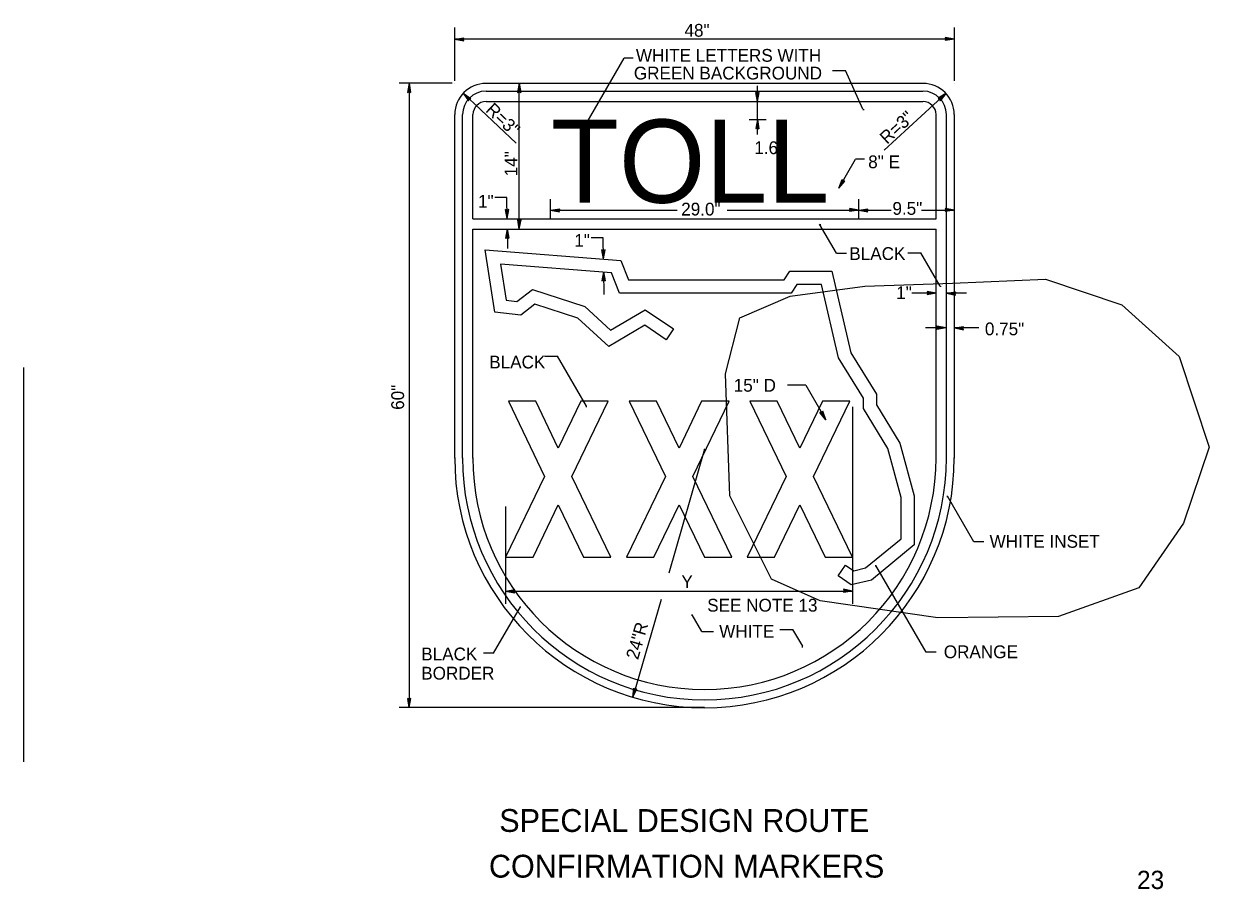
# Model space of a CAD drawing. Extents: x 51788 to 52424, y 9835 to 10249.
# Drawn here: x 52164.7 to 52424.2, y 9845.3 to 10034.8 of the extents above; entities that cross this region are included whole.
import ezdxf

# ---------------------------------------------------------------- set-up
doc = ezdxf.new("R2010")
doc.units = 0
for name, color, linetype in [('DimLines_dp', 7, 'Continuous'), ('GSColorFill', 7, 'Continuous'), ('GSDims', 7, 'Continuous'), ('SignPanel', 7, 'Continuous'), ('TextAlert', 7, 'Continuous'), ('TextMisc', 7, 'Continuous'), ('TextShtNo', 7, 'Continuous')]:
    doc.layers.add(name, color=color, linetype=linetype)

msp = doc.modelspace()

# ---------------------------------------------------------------- linework, layer by layer
at = {"layer": 'DimLines_dp'}
msp.add_line((52313.7, 9941.63), (52313.7, 9941.63), dxfattribs=at)
msp.add_line((52313.7, 9941.63), (52313.7, 9941.63), dxfattribs=at)
for radius in [0.0387, 0.0387, 0.0193]:
    msp.add_circle((52313.7, 9941.63), radius, dxfattribs=at)
at = {"layer": 'GSColorFill'}
for p, q in [((52270.76, 9952.16), (52278.69, 9935.69)), ((52276.75, 9952.16), (52270.76, 9952.16)), ((52270.76, 9952.16), (52278.69, 9935.69)), ((52276.75, 9952.16), (52270.76, 9952.16)), ((52281.69, 9941.91), (52276.75, 9952.16)), ((52281.69, 9941.91), (52276.75, 9952.16)), ((52286.63, 9952.16), (52281.69, 9941.91)), ((52286.63, 9952.16), (52281.69, 9941.91)), ((52284.69, 9935.69), (52292.63, 9952.16)), ((52284.69, 9935.69), (52292.63, 9952.16)), ((52292.63, 9952.16), (52286.63, 9952.16)), ((52292.63, 9952.16), (52286.63, 9952.16)), ((52297.2, 9952.16), (52305.13, 9935.69)), ((52303.19, 9952.16), (52297.2, 9952.16)), ((52297.2, 9952.16), (52305.13, 9935.69)), ((52303.19, 9952.16), (52297.2, 9952.16)), ((52308.13, 9941.91), (52303.19, 9952.16)), ((52308.13, 9941.91), (52303.19, 9952.16)), ((52313.07, 9952.16), (52308.13, 9941.91)), ((52313.07, 9952.16), (52308.13, 9941.91)), ((52311.13, 9935.69), (52319.07, 9952.16)), ((52311.13, 9935.69), (52319.07, 9952.16)), ((52319.07, 9952.16), (52313.07, 9952.16)), ((52319.07, 9952.16), (52313.07, 9952.16)), ((52323.64, 9952.16), (52331.58, 9935.69)), ((52329.63, 9952.16), (52323.64, 9952.16)), ((52323.64, 9952.16), (52331.58, 9935.69)), ((52329.63, 9952.16), (52323.64, 9952.16)), ((52334.57, 9941.91), (52329.63, 9952.16)), ((52334.57, 9941.91), (52329.63, 9952.16)), ((52339.51, 9952.16), (52334.57, 9941.91)), ((52339.51, 9952.16), (52334.57, 9941.91)), ((52337.57, 9935.69), (52345.51, 9952.16)), ((52337.57, 9935.69), (52345.51, 9952.16)), ((52345.51, 9952.16), (52339.51, 9952.16)), ((52345.51, 9952.16), (52339.51, 9952.16)), ((52278.69, 9935.69), (52270.16, 9917.99)), ((52278.69, 9935.69), (52270.16, 9917.99)), ((52293.22, 9917.99), (52284.69, 9935.69)), ((52293.22, 9917.99), (52284.69, 9935.69)), ((52305.13, 9935.69), (52296.6, 9917.99)), ((52305.13, 9935.69), (52296.6, 9917.99)), ((52319.66, 9917.99), (52311.13, 9935.69)), ((52319.66, 9917.99), (52311.13, 9935.69)), ((52331.58, 9935.69), (52323.05, 9917.99)), ((52331.58, 9935.69), (52323.05, 9917.99)), ((52346.1, 9917.99), (52337.57, 9935.69)), ((52346.1, 9917.99), (52337.57, 9935.69)), ((52276.16, 9917.99), (52281.69, 9929.47)), ((52276.16, 9917.99), (52281.69, 9929.47)), ((52281.69, 9929.47), (52287.22, 9917.99)), ((52281.69, 9929.47), (52287.22, 9917.99)), ((52302.6, 9917.99), (52308.13, 9929.47)), ((52302.6, 9917.99), (52308.13, 9929.47)), ((52308.13, 9929.47), (52313.67, 9917.99)), ((52308.13, 9929.47), (52313.67, 9917.99)), ((52329.04, 9917.99), (52334.57, 9929.47)), ((52329.04, 9917.99), (52334.57, 9929.47)), ((52334.57, 9929.47), (52340.11, 9917.99)), ((52334.57, 9929.47), (52340.11, 9917.99)), ((52270.16, 9917.99), (52276.16, 9917.99)), ((52270.16, 9917.99), (52276.16, 9917.99)), ((52287.22, 9917.99), (52293.22, 9917.99)), ((52287.22, 9917.99), (52293.22, 9917.99)), ((52296.6, 9917.99), (52302.6, 9917.99)), ((52296.6, 9917.99), (52302.6, 9917.99)), ((52313.67, 9917.99), (52319.66, 9917.99)), ((52313.67, 9917.99), (52319.66, 9917.99)), ((52323.05, 9917.99), (52329.04, 9917.99)), ((52323.05, 9917.99), (52329.04, 9917.99)), ((52340.11, 9917.99), (52346.1, 9917.99)), ((52340.11, 9917.99), (52346.1, 9917.99))]:
    msp.add_line(p, q, dxfattribs=at)
for points in [[(52270.76, 9952.16), (52278.69, 9935.69), (52270.16, 9917.99), (52276.16, 9917.99), (52281.69, 9929.47), (52287.22, 9917.99), (52293.22, 9917.99), (52284.69, 9935.69), (52292.63, 9952.16), (52286.63, 9952.16), (52281.69, 9941.91), (52276.75, 9952.16)], [(52297.2, 9952.16), (52305.13, 9935.69), (52296.6, 9917.99), (52302.6, 9917.99), (52308.13, 9929.47), (52313.67, 9917.99), (52319.66, 9917.99), (52311.13, 9935.69), (52319.07, 9952.16), (52313.07, 9952.16), (52308.13, 9941.91), (52303.19, 9952.16)], [(52323.64, 9952.16), (52331.58, 9935.69), (52323.05, 9917.99), (52329.04, 9917.99), (52334.57, 9929.47), (52340.11, 9917.99), (52346.1, 9917.99), (52337.57, 9935.69), (52345.51, 9952.16), (52339.51, 9952.16), (52334.57, 9941.91), (52329.63, 9952.16)]]:
    msp.add_lwpolyline(points, close=True, dxfattribs=at)
at = {"layer": 'GSDims'}
for p, q in [((52259.03, 10022.32), (52259.03, 10033.96)), ((52368.39, 10022.32), (52368.39, 10033.96)), ((52259.03, 10031.43), (52261.03, 10031.75)), ((52259.03, 10031.43), (52260.95, 10031.57)), ((52259.03, 10031.43), (52261.02, 10031.05)), ((52259.03, 10031.43), (52260.95, 10031.23)), ((52368.39, 10031.43), (52259.03, 10031.43)), ((52260.88, 10031.41), (52261.03, 10031.75)), ((52261.02, 10031.05), (52260.88, 10031.41)), ((52366.54, 10031.46), (52366.39, 10031.12)), ((52368.39, 10031.43), (52366.39, 10031.12)), ((52368.39, 10031.43), (52366.4, 10031.82)), ((52366.4, 10031.82), (52366.54, 10031.46)), ((52368.39, 10031.43), (52366.47, 10031.64)), ((52368.39, 10031.43), (52366.47, 10031.3)), ((52286.9, 10011.34), (52296.1, 10027.25)), ((52298.07, 10027.25), (52296.1, 10027.25)), ((52341.7, 10024.55), (52344.56, 10024.55)), ((52348.37, 10016.08), (52344.56, 10024.55)), ((52258.47, 10021.76), (52246.83, 10021.76)), ((52249.04, 10021.76), (52248.66, 10019.77)), ((52249.04, 10021.76), (52248.84, 10019.84)), ((52249.04, 10021.76), (52249.36, 10019.76)), ((52249.04, 10021.76), (52249.18, 10019.84)), ((52249.04, 10021.76), (52249.04, 9885.07)), ((52259.03, 10021.76), (52259.03, 10021.76)), ((52273.15, 10021.76), (52272.77, 10019.77)), ((52273.15, 10021.76), (52272.95, 10019.84)), ((52273.15, 10021.76), (52273.47, 10019.76)), ((52273.15, 10021.76), (52273.29, 10019.84)), ((52273.15, 9989.85), (52273.15, 10021.76)), ((52325.29, 10017.77), (52325.29, 10021.21)), ((52368.39, 10021.76), (52368.39, 10021.76)), ((52248.66, 10019.77), (52249.01, 10019.91)), ((52249.01, 10019.91), (52249.36, 10019.76)), ((52260.89, 10019.6), (52262.56, 10018.46)), ((52260.89, 10019.6), (52262.07, 10017.96)), ((52260.89, 10019.6), (52262.15, 10018.15)), ((52260.89, 10019.6), (52262.38, 10018.38)), ((52260.89, 10019.6), (52272.48, 10008.67)), ((52262.07, 10017.96), (52262.2, 10018.31)), ((52262.2, 10018.31), (52262.56, 10018.46)), ((52272.77, 10019.77), (52273.13, 10019.91)), ((52273.13, 10019.91), (52273.47, 10019.76)), ((52325.29, 10017.77), (52324.97, 10019.76)), ((52325.31, 10019.61), (52324.97, 10019.76)), ((52325.29, 10017.77), (52325.15, 10019.68)), ((52325.29, 10017.77), (52325.67, 10019.75)), ((52325.29, 10017.77), (52325.49, 10019.68)), ((52325.67, 10019.75), (52325.31, 10019.61)), ((52366.55, 10019.54), (52353.05, 10007.11)), ((52366.55, 10019.54), (52364.83, 10018.48)), ((52364.83, 10018.48), (52365.17, 10018.31)), ((52366.55, 10019.54), (52365.01, 10018.39)), ((52365.17, 10018.31), (52365.3, 10017.96)), ((52366.55, 10019.54), (52365.24, 10018.15)), ((52366.55, 10019.54), (52365.3, 10017.96)), ((52325.29, 10013.83), (52325.29, 10017.77)), ((52323.48, 10013.83), (52327.21, 10013.83)), ((52325.29, 10013.83), (52324.9, 10011.85)), ((52325.29, 10013.83), (52325.08, 10011.92)), ((52325.29, 10010.55), (52325.29, 10013.83)), ((52325.29, 10013.83), (52325.6, 10011.83)), ((52325.29, 10013.83), (52325.42, 10011.92)), ((52324.9, 10011.85), (52325.26, 10011.98)), ((52325.26, 10011.98), (52325.6, 10011.83)), ((52343.07, 9998.82), (52346.73, 10005.16)), ((52348.7, 10005.16), (52346.73, 10005.16)), ((52343.07, 9998.82), (52343.8, 10000.71)), ((52343.07, 9998.82), (52343.92, 10000.54)), ((52343.07, 9998.82), (52344.21, 10000.38)), ((52343.07, 9998.82), (52344.4, 10000.35)), ((52344.01, 10000.39), (52343.8, 10000.71)), ((52344.4, 10000.35), (52344.01, 10000.39)), ((52270.46, 9996.78), (52267.8, 9996.78)), ((52270.5, 9992.15), (52270.46, 9996.78)), ((52280, 9992.12), (52280, 9996.39)), ((52347.45, 9992.12), (52347.45, 9996.39)), ((52270.5, 9992.15), (52270.16, 9994.15)), ((52270.52, 9993.99), (52270.16, 9994.15)), ((52270.5, 9992.15), (52270.35, 9994.06)), ((52270.5, 9992.15), (52270.87, 9994.15)), ((52270.5, 9992.15), (52270.68, 9994.06)), ((52270.87, 9994.15), (52270.52, 9993.99)), ((52280, 9993.98), (52282, 9994.3)), ((52280, 9993.98), (52281.92, 9994.12)), ((52280, 9993.98), (52281.98, 9993.6)), ((52280, 9993.98), (52281.92, 9993.78)), ((52280, 9993.98), (52307.7, 9993.98)), ((52281.85, 9993.95), (52282, 9994.3)), ((52281.98, 9993.6), (52281.85, 9993.95)), ((52318.68, 9993.98), (52347.45, 9993.98)), ((52345.6, 9994.01), (52345.45, 9993.67)), ((52347.45, 9993.98), (52345.45, 9993.67)), ((52347.45, 9993.98), (52345.46, 9994.36)), ((52345.46, 9994.36), (52345.6, 9994.01)), ((52347.45, 9993.98), (52345.53, 9994.19)), ((52347.45, 9993.98), (52345.53, 9993.84)), ((52347.45, 9993.98), (52349.44, 9994.3)), ((52347.45, 9993.98), (52349.36, 9994.12)), ((52347.45, 9993.98), (52349.43, 9993.6)), ((52347.45, 9993.98), (52349.36, 9993.78)), ((52347.45, 9993.98), (52354.57, 9993.98)), ((52349.29, 9993.95), (52349.44, 9994.3)), ((52349.43, 9993.6), (52349.29, 9993.95)), ((52361.22, 9993.98), (52368.39, 9993.98)), ((52366.54, 9994.01), (52366.39, 9993.67)), ((52368.39, 9993.98), (52366.39, 9993.67)), ((52368.39, 9993.98), (52366.4, 9994.36)), ((52366.4, 9994.36), (52366.54, 9994.01)), ((52368.39, 9993.98), (52366.47, 9994.19)), ((52368.39, 9993.98), (52366.47, 9993.84)), ((52270.53, 9989.88), (52270.16, 9987.88)), ((52270.53, 9989.88), (52270.35, 9987.97)), ((52270.53, 9989.88), (52270.87, 9987.88)), ((52270.53, 9989.88), (52270.68, 9987.97)), ((52270.53, 9989.88), (52270.58, 9985.56)), ((52273.15, 9989.85), (52272.84, 9991.85)), ((52273.18, 9991.7), (52272.84, 9991.85)), ((52273.15, 9989.85), (52273.02, 9991.77)), ((52273.15, 9989.85), (52273.54, 9991.84)), ((52273.15, 9989.85), (52273.36, 9991.77)), ((52273.54, 9991.84), (52273.18, 9991.7)), ((52342.57, 9984.58), (52338.9, 9990.92)), ((52270.16, 9987.88), (52270.52, 9988.04)), ((52270.52, 9988.04), (52270.87, 9987.88)), ((52291.53, 9987.93), (52288.86, 9987.93)), ((52291.57, 9983.3), (52291.53, 9987.93)), ((52291.57, 9983.3), (52291.23, 9985.29)), ((52291.58, 9985.14), (52291.23, 9985.29)), ((52291.57, 9983.3), (52291.42, 9985.21)), ((52291.57, 9983.3), (52291.94, 9985.29)), ((52291.57, 9983.3), (52291.75, 9985.21)), ((52291.94, 9985.29), (52291.58, 9985.14)), ((52342.57, 9984.58), (52344.8, 9984.58)), ((52358.22, 9984.67), (52361.07, 9984.67)), ((52365.31, 9977.35), (52361.07, 9984.67)), ((52291.6, 9980.48), (52291.23, 9978.48)), ((52291.6, 9980.48), (52291.42, 9978.56)), ((52291.6, 9980.48), (52291.94, 9978.48)), ((52291.6, 9980.48), (52291.75, 9978.56)), ((52291.6, 9980.48), (52291.65, 9975.54)), ((52291.23, 9978.48), (52291.58, 9978.63)), ((52291.58, 9978.63), (52291.94, 9978.48)), ((52364.42, 9975.79), (52359.08, 9975.79)), ((52362.58, 9975.81), (52362.43, 9975.47)), ((52364.42, 9975.79), (52362.43, 9975.47)), ((52364.42, 9975.79), (52362.44, 9976.17)), ((52362.44, 9976.17), (52362.58, 9975.81)), ((52364.42, 9975.79), (52362.51, 9975.99)), ((52364.42, 9975.79), (52362.51, 9975.65)), ((52366.69, 9975.79), (52368.69, 9976.1)), ((52366.69, 9975.79), (52368.6, 9975.92)), ((52366.69, 9975.79), (52368.67, 9975.4)), ((52366.69, 9975.79), (52368.6, 9975.58)), ((52371.07, 9975.79), (52366.69, 9975.79)), ((52368.54, 9975.76), (52368.69, 9976.1)), ((52368.67, 9975.4), (52368.54, 9975.76)), ((52366.57, 9968.19), (52364.59, 9968.57)), ((52364.59, 9968.57), (52364.72, 9968.21)), ((52366.57, 9968.19), (52362.06, 9968.19)), ((52364.72, 9968.21), (52364.57, 9967.87)), ((52366.57, 9968.19), (52364.57, 9967.87)), ((52366.57, 9968.19), (52364.65, 9968.39)), ((52366.57, 9968.19), (52364.65, 9968.05)), ((52368.39, 9968.19), (52370.38, 9968.5)), ((52368.39, 9968.19), (52370.3, 9968.32)), ((52368.39, 9968.19), (52370.37, 9967.8)), ((52368.39, 9968.19), (52370.3, 9967.98)), ((52373.73, 9968.19), (52368.39, 9968.19)), ((52370.23, 9968.16), (52370.38, 9968.5)), ((52370.37, 9967.8), (52370.23, 9968.16)), ((52278.69, 9961.99), (52281.55, 9961.99)), ((52287.87, 9951.07), (52281.55, 9961.99)), ((52335.87, 9955.67), (52331.87, 9955.67)), ((52335.87, 9955.67), (52340.24, 9948.09)), ((52346.1, 9950.96), (52346.1, 9907.82)), ((52339.35, 9949.69), (52338.97, 9949.66)), ((52340.24, 9948.09), (52338.97, 9949.66)), ((52340.24, 9948.09), (52339.17, 9949.69)), ((52339.58, 9950), (52339.35, 9949.69)), ((52340.24, 9948.09), (52339.46, 9949.85)), ((52340.24, 9948.09), (52339.58, 9950)), ((52313.7, 9941.63), (52305.87, 9914.51)), ((52372.66, 9921.34), (52366.88, 9931.36)), ((52270.16, 9929.11), (52270.16, 9907.82)), ((52374.87, 9921.34), (52372.66, 9921.34)), ((52362.19, 9897.23), (52351.22, 9916.21)), ((52270.16, 9910.58), (52272.16, 9910.9)), ((52270.16, 9910.58), (52272.08, 9910.72)), ((52270.16, 9910.58), (52272.15, 9910.2)), ((52270.16, 9910.58), (52272.08, 9910.38)), ((52270.16, 9910.58), (52346.1, 9910.58)), ((52272.01, 9910.56), (52272.16, 9910.9)), ((52272.15, 9910.2), (52272.01, 9910.56)), ((52344.26, 9910.61), (52344.11, 9910.27)), ((52346.1, 9910.58), (52344.11, 9910.27)), ((52346.1, 9910.58), (52344.12, 9910.97)), ((52344.12, 9910.97), (52344.26, 9910.61)), ((52346.1, 9910.58), (52344.19, 9910.79)), ((52346.1, 9910.58), (52344.19, 9910.45)), ((52267.52, 9896.97), (52273.41, 9907.16)), ((52304.21, 9908.76), (52298.03, 9887.34)), ((52313.1, 9901.77), (52311.02, 9905.36)), ((52313.1, 9901.77), (52315.7, 9901.77)), ((52330.21, 9902.19), (52333.07, 9902.19)), ((52335.2, 9898.5), (52333.07, 9902.19)), ((52267.52, 9896.97), (52265.32, 9896.97)), ((52364.39, 9897.23), (52362.19, 9897.23)), ((52298.03, 9887.34), (52298.21, 9889.35)), ((52298.03, 9887.34), (52298.37, 9889.24)), ((52298.03, 9887.34), (52298.89, 9889.17)), ((52298.03, 9887.34), (52298.7, 9889.15)), ((52298.21, 9889.35), (52298.52, 9889.12)), ((52298.52, 9889.12), (52298.89, 9889.17)), ((52249.04, 9885.07), (52248.73, 9887.06)), ((52249.07, 9886.91), (52248.73, 9887.06)), ((52249.04, 9885.07), (52248.9, 9886.98)), ((52249.04, 9885.07), (52249.42, 9887.05)), ((52249.04, 9885.07), (52249.25, 9886.98)), ((52249.42, 9887.05), (52249.07, 9886.91)), ((52313.68, 9885.07), (52246.83, 9885.07)), ((52259.03, 9885.04), (52259.03, 9885.04))]:
    msp.add_line(p, q, dxfattribs=at)
msp.add_lwpolyline([(52321.45, 9970.42), (52332.45, 9975.14), (52348.79, 9977.34), (52367.95, 9977.97), (52388.38, 9978.91), (52405.03, 9973.25), (52417.6, 9961.93), (52424.2, 9942.12), (52418.54, 9925.45), (52408.8, 9911.3), (52391.21, 9905.01), (52364.81, 9904.7), (52339.05, 9908.47), (52328.36, 9913.19), (52319.25, 9931.43), (52318.31, 9958.16), (52321.45, 9970.42)], dxfattribs=at)
at = {"layer": 'SignPanel'}
for p, q in [((52265.87, 10021.76), (52361.52, 10021.76)), ((52265.87, 10020.03), (52361.52, 10020.03)), ((52265.87, 10017.77), (52361.52, 10017.77)), ((52259.01, 9939.71), (52259.03, 10014.92)), ((52260.7, 9939.71), (52260.73, 10014.92)), ((52263, 9992.12), (52263, 10014.92)), ((52364.42, 9992.12), (52364.42, 10014.92)), ((52366.69, 9939.71), (52366.69, 10014.92)), ((52368.39, 9939.71), (52368.39, 10014.92)), ((52263, 9992.12), (52277.27, 9992.12)), ((52277.27, 9992.12), (52364.42, 9992.12)), ((52262.97, 9939.71), (52263, 9989.85)), ((52263, 9989.85), (52364.42, 9989.85)), ((52364.42, 9939.71), (52364.42, 9989.85)), ((52267.8, 9971.68), (52265.68, 9985.27)), ((52265.68, 9985.27), (52295.38, 9982.98)), ((52293.37, 9980.26), (52269.07, 9982.14)), ((52269.07, 9982.14), (52270.29, 9974.26)), ((52295.38, 9982.98), (52297.05, 9978.71)), ((52295.09, 9975.84), (52293.37, 9980.26)), ((52331.12, 9978.71), (52332.4, 9980.6)), ((52332.4, 9980.6), (52341.57, 9980.6)), ((52341.57, 9980.6), (52345.72, 9962.75)), ((52272.65, 9973.97), (52276.02, 9976.63)), ((52276.02, 9976.63), (52287.48, 9972.9)), ((52297.05, 9978.71), (52331.12, 9978.71)), ((52333.92, 9977.74), (52332.64, 9975.84)), ((52339.29, 9977.74), (52333.92, 9977.74)), ((52343.03, 9961.64), (52339.29, 9977.74)), ((52270.29, 9974.26), (52272.65, 9973.97)), ((52332.64, 9975.84), (52295.09, 9975.84)), ((52273.48, 9970.98), (52267.8, 9971.68)), ((52276.59, 9973.43), (52273.48, 9970.98)), ((52286, 9970.37), (52276.59, 9973.43)), ((52287.48, 9972.9), (52293.11, 9967.69)), ((52293.11, 9967.69), (52300.73, 9972.17)), ((52300.73, 9972.17), (52306.94, 9967.97)), ((52292.72, 9964.14), (52286, 9970.37)), ((52300.63, 9968.78), (52292.72, 9964.14)), ((52305.33, 9965.6), (52300.63, 9968.78)), ((52306.94, 9967.97), (52305.33, 9965.6)), ((52348.5, 9952.85), (52343.03, 9961.64)), ((52345.72, 9962.75), (52351.36, 9953.67)), ((52351.36, 9953.67), (52351.36, 9951.38)), ((52348.5, 9950.58), (52348.5, 9952.85)), ((52353.82, 9941.82), (52348.5, 9950.58)), ((52351.36, 9951.38), (52356.48, 9942.96)), ((52356.48, 9942.96), (52359.62, 9931.45)), ((52356.76, 9931.07), (52353.82, 9941.82)), ((52356.76, 9922.05), (52356.76, 9931.07)), ((52359.62, 9931.45), (52359.62, 9920.69)), ((52348.93, 9915.64), (52356.76, 9922.05)), ((52359.62, 9920.69), (52350.24, 9913)), ((52342.96, 9913.9), (52344.59, 9916.25)), ((52344.59, 9916.25), (52346.36, 9915.02)), ((52346.36, 9915.02), (52348.93, 9915.64)), ((52345.78, 9911.94), (52342.96, 9913.9)), ((52350.24, 9913), (52345.78, 9911.94))]:
    msp.add_line(p, q, dxfattribs=at)
for centre, radius, start, end in [((52265.87, 10014.91), 6.83, 90, 179.9792), ((52361.53, 10014.91), 6.83, 0, 90), ((52265.87, 10014.91), 5.13, 90, 179.9792), ((52361.53, 10014.91), 5.13, 0, 90), ((52265.87, 10014.91), 2.85, 90, 179.9792), ((52361.53, 10014.91), 2.85, 0, 90), ((52313.69, 9939.73), 54.68, 180, 0), ((52313.69, 9939.73), 52.97, 180, 0), ((52313.69, 9939.73), 50.69, 180, 0)]:
    msp.add_arc(centre, radius, start, end, dxfattribs=at)
at = {"layer": 'TextAlert'}
msp.add_line((52164.67, 9873.2), (52164.67, 9959.57), dxfattribs=at)

# ---------------------------------------------------------------- texts
at = {"layer": 'DimLines_dp'}
msp.add_text('.', height=2.3, rotation=90, dxfattribs=at).set_placement((52313.98, 9941.13))
at = {"layer": 'GSDims'}
for s, height, p in [('48"', 2.8, (52309.32, 10031.97)), ('WHITE LETTERS WITH', 2.8, (52298.68, 10026.48)), ('GREEN BACKGROUND', 2.8, (52298.23, 10022.6)), ('.', 2.3, (52286.58, 10011.03)), ('1.6"', 2.8, (52324.59, 10006.26)), ('8" E ', 2.8, (52349.53, 10003.17)), ('1"', 2.8, (52264.13, 9994.54)), ('29.0"', 2.8, (52308.6, 9992.82)), ('9.5"', 2.8, (52354.84, 9992.97)), ('1"', 2.8, (52285.2, 9985.96)), ('BLACK', 2.8, (52345.4, 9983.08)), ('1"', 2.8, (52355.66, 9974.51)), ('0.75"', 2.8, (52375.08, 9966.59)), ('BLACK', 2.8, (52266.58, 9959.33)), ('15" D', 2.8, (52320.09, 9954.24)), ('.', 2.3, (52287.4, 9950.79)), ('WHITE INSET', 2.8, (52376.11, 9920.07)), ('.', 2.3, (52350.73, 9915.96)), ('Y', 2.8, (52308.64, 9911.26)), ('SEE NOTE 13', 2.8, (52314.29, 9906.09)), ('.', 2.3, (52272.92, 9906.92)), ('.', 2.3, (52310.54, 9905.1)), ('WHITE', 2.8, (52316.91, 9900.39)), ('.', 2.3, (52334.7, 9898.22)), ('ORANGE', 2.8, (52366.08, 9895.89)), ('BLACK', 2.8, (52251.69, 9895.41)), ('BORDER', 2.8, (52251.69, 9891.21))]:
    msp.add_text(s, height=height, dxfattribs=at).set_placement(p)
for s, height, rotation, p in [('R=3"', 2.8, 316.6507, (52265.61, 10015.71)), ('.', 2.3, 90, (52348.67, 10015.58)), ('R=3"', 2.8, 42.6037, (52353.65, 10008.28)), ('14"', 2.8, 90, (52272.74, 10001.4)), ('.', 1.97, 90, (52365.55, 9976.9)), ('60"', 2.8, 90, (52247.93, 9950.27)), ('24"R', 2.8, 73.9233, (52299.14, 9895.41))]:
    msp.add_text(s, height=height, rotation=rotation, dxfattribs=at).set_placement(p)
at = {"layer": 'SignPanel'}
for s, height, p in [('TOLL', 18.221, (52280.07, 9995.61)), ('.', 2.3, (52366.4, 9931.09))]:
    msp.add_text(s, height=height, dxfattribs=at).set_placement(p)
msp.add_text('.', height=2.3, rotation=90, dxfattribs=at).set_placement((52339.18, 9990.38))
at = {"layer": 'TextMisc'}
for s, p in [('  SPECIAL DESIGN ROUTE  ', (52265.05, 9857.85)), ('  CONFIRMATION MARKERS  ', (52262.79, 9847.85))]:
    msp.add_text(s, height=5, rotation=360, dxfattribs=at).set_placement(p)
at = {"layer": 'TextShtNo'}
msp.add_text('23', height=4, rotation=360, dxfattribs=at).set_placement((52408.37, 9845.35))

doc.saveas('drawing.dxf')
